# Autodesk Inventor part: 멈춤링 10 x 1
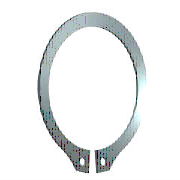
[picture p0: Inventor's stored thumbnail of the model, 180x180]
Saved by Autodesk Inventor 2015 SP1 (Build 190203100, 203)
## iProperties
IsCustomPart: 0
Company: 한국ATC센터
Created: 2014-07
Part Number: 멈춤링 10 x 1
Material: Steel, Mild
Description: 리테이닝 링(C형)
Document SubType Name: Modeling
Standard: KS B 1336
Designer: KYOUNG IL JANG
Standards Organization: KS
Language: ko-KR
Size Designation: 10 x 1
Categories: <MemberInstance><Categories><Category DisplayName="샤프트 부품" InternalName="7f7aeb1f-a693-4053-b835-cee3144e0d98" Mnemonic="SHFT"><Category DisplayName="써클립" Inter
Density: 7.86 g/cm^3
Appearance: Metal-Steel
Mass: 0.423087 g
Surface Area: 1.9243 cm^2
Volume: 0.0538279 cm^3
Author: KYOUNG IL JANG
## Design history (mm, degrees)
sketch "스케치1"
  geometry: L1 (-6, 0)-(6, 0) reference; L2 (0, 20.189)-(0, -80.536) reference; L3 (-48.09, 0)-(48.09, 0) reference; L4 (-0.3, -9.791)-(-0.3, -12.791); L5 (-0.3, -6.54)-(-0.3, -13.29); L6 (-2.795, 1.6)-(3.672, 1.6); L7 (0.3, -6.54)-(0.3, -13.29); L8 (0.3, -9.791)-(0.3, -12.791); C1 r 0.6 at (-1.2, -11.486); C2 r 0.6 at (1.2, -11.486); A1 r 4.8 centre (0, -5) between (0.3, -9.791) and (-0.3, -9.791); A2 r 6.2 centre (0, -4.6) between (2.988, -10.033) and (-2.988, -10.033); A3 r 7.796 centre (0, -5) between (-1.418, -12.666) and (-0.3, -12.791); A4 r 1.2 centre (-1.2, -11.486) between (-2.383, -11.285) and (-1.418, -12.666); A5 r 1.2 centre (-3.566, -11.084) between (-2.383, -11.285) and (-2.988, -10.033); A6 r 1.2 centre (3.566, -11.084) between (2.988, -10.033) and (2.383, -11.285); A7 r 1.2 centre (1.2, -11.486) between (1.418, -12.666) and (2.383, -11.285); A8 r 7.796 centre (0, -5) between (0.3, -12.791) and (1.418, -12.666)
  constraints: 16 point on circle, 12 end point, 10 centre point, 9 symmetric about line, 5 point on line, 4 tangent, 3 coincident, 2 horizontal, 1 perpendicular, 1 vertical, 5 other
  dimensions: "d0" = 9.6 diameter of A1 (= ND); "d1" = 3 distance of L4.end L4.start (= SRB2); "d6" = 0.3 distance between parallel lines of L2 L5 (= 0.25 x SD5); "d7" = 1.6 distance between parallel lines of L6 L3 (= SRB1); "d8" = 0.4 distance of A1.centre A2.centre (= 0.25 x SRB1); "d9" = 1.2 radius of A4 (= SD5); "d10" = 1.2 radius of A5 (= SD5); "d11" = 0.9 distance from line of L4 A4.centre (= 0.75 x SD5); "d12" = 1.2 diameter of C1 (= SD5); "d13" = 1.2 diameter of C2 (= SD5); "d14" = 5 distance from line of A1.centre L1 (= 0.5 x WD)
extrude "본체" new body sketch "스케치1" distance "d2" = 1 (= SD); taper "d3" = 0 deg
workaxis "Work Axis1"
workplane "Work Plane1"
body "Solid1"
other parameters: "SD" = 1 [user parameter; used in 1 equation term], "SRB1" = 1.6 [user parameter; used in 2 equation terms], "ND" = 9.6 [user parameter; used in 1 equation term], "SRB2" = 3 [user parameter; used in 1 equation term], "SD5" = 1.2 [user parameter; used in 6 equation terms], "d15" = 0, "d16" = 0, "d17" = 0, "d41" = 0, "d42" = 0, "SD3" = 9.3 [user parameter], "WDMAX" = 11 [user parameter]
